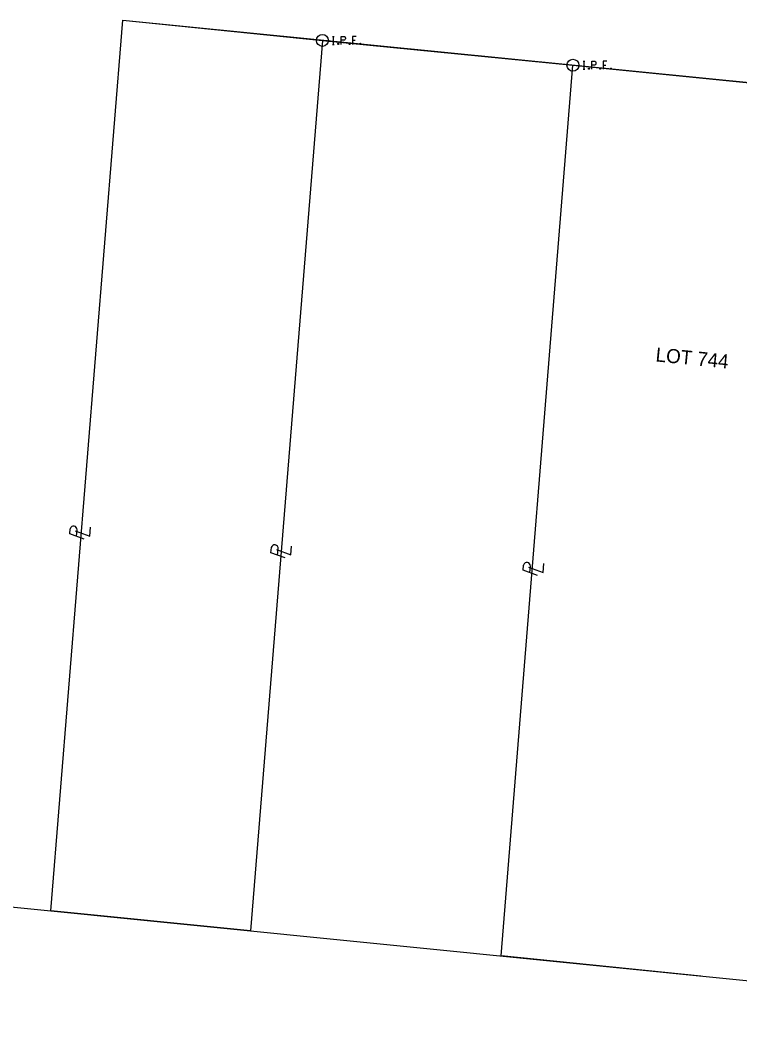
# Model space of a CAD drawing. Extents: x 204354 to 231038, y 361459 to 365260.
# Drawn here: x 220294.5 to 220438, y 363483.6 to 363685.1 of the extents above; entities that cross this region are included whole.
import ezdxf

# ---------------------------------------------------------------- set-up
doc = ezdxf.new("R2010")
doc.units = 0
for name, color, linetype in [('Default', 7, 'Continuous'), ('MD_P_Surface_Finished_Grade', 7, 'Continuous'), ('MD_P_SW_BOT', 7, 'Continuous'), ('PV_P_Walk', 7, 'Continuous')]:
    doc.layers.add(name, color=color, linetype=linetype)

msp = doc.modelspace()

# ---------------------------------------------------------------- linework, layer by layer
at = {"layer": 'MD_P_Surface_Finished_Grade'}
for points in [[(220356.8, 363681.84), (220357.15, 363681.84)], [(220356.98, 363680.24), (220356.98, 363681.84)], [(220358.54, 363680.24), (220358.54, 363681.84), (220359.07, 363681.84), (220359.13, 363681.83), (220359.2, 363681.8), (220359.24, 363681.78), (220359.27, 363681.75), (220359.31, 363681.69), (220359.35, 363681.62), (220359.37, 363681.52), (220359.37, 363681.37), (220359.36, 363681.32), (220359.34, 363681.25), (220359.29, 363681.16), (220359.25, 363681.12), (220359.22, 363681.1), (220359.16, 363681.07), (220359.07, 363681.06), (220358.54, 363681.06)], [(220361.55, 363681.84), (220360.79, 363681.84), (220360.79, 363680.24)], [(220356.8, 363680.24), (220357.15, 363680.24)], [(220357.94, 363680.45), (220357.99, 363680.45), (220358.03, 363680.43), (220358.06, 363680.38), (220358.06, 363680.31), (220358.03, 363680.26), (220357.99, 363680.24), (220357.94, 363680.24), (220357.9, 363680.26), (220357.87, 363680.31), (220357.87, 363680.38), (220357.9, 363680.43), (220357.94, 363680.45)], [(220360.19, 363680.45), (220360.24, 363680.45), (220360.27, 363680.43), (220360.31, 363680.38), (220360.31, 363680.31), (220360.27, 363680.26), (220360.24, 363680.24), (220360.19, 363680.24), (220360.15, 363680.26), (220360.12, 363680.31), (220360.12, 363680.38), (220360.15, 363680.43), (220360.19, 363680.45)], [(220360.79, 363681.06), (220361.33, 363681.06)], [(220362.33, 363680.45), (220362.39, 363680.45), (220362.42, 363680.43), (220362.46, 363680.38), (220362.46, 363680.31), (220362.42, 363680.26), (220362.39, 363680.24), (220362.33, 363680.24), (220362.3, 363680.26), (220362.27, 363680.31), (220362.27, 363680.38), (220362.3, 363680.43), (220362.33, 363680.45)], [(220406.78, 363676.88), (220407.13, 363676.88)], [(220406.96, 363675.28), (220406.96, 363676.88)], [(220407.91, 363675.49), (220407.97, 363675.49), (220408, 363675.47), (220408.04, 363675.41), (220408.04, 363675.35), (220408, 363675.3), (220407.97, 363675.28), (220407.91, 363675.28), (220407.88, 363675.3), (220407.85, 363675.35), (220407.85, 363675.41), (220407.88, 363675.47), (220407.91, 363675.49)], [(220408.52, 363675.28), (220408.52, 363676.88), (220409.05, 363676.88), (220409.11, 363676.86), (220409.18, 363676.84), (220409.22, 363676.81), (220409.25, 363676.79), (220409.29, 363676.72), (220409.33, 363676.66), (220409.35, 363676.56), (220409.35, 363676.41), (220409.34, 363676.36), (220409.31, 363676.28), (220409.27, 363676.2), (220409.23, 363676.16), (220409.19, 363676.13), (220409.14, 363676.11), (220409.05, 363676.09), (220408.52, 363676.09)], [(220410.16, 363675.49), (220410.22, 363675.49), (220410.25, 363675.47), (220410.28, 363675.41), (220410.28, 363675.35), (220410.25, 363675.3), (220410.22, 363675.28), (220410.16, 363675.28), (220410.13, 363675.3), (220410.1, 363675.35), (220410.1, 363675.41), (220410.13, 363675.47), (220410.16, 363675.49)], [(220411.53, 363676.88), (220410.77, 363676.88), (220410.77, 363675.28)], [(220410.77, 363676.09), (220411.31, 363676.09)], [(220412.31, 363675.49), (220412.37, 363675.49), (220412.4, 363675.47), (220412.43, 363675.41), (220412.43, 363675.35), (220412.4, 363675.3), (220412.37, 363675.28), (220412.31, 363675.28), (220412.28, 363675.3), (220412.25, 363675.35), (220412.25, 363675.41), (220412.28, 363675.47), (220412.31, 363675.49)], [(220406.78, 363675.28), (220407.13, 363675.28)]]:
    msp.add_lwpolyline(points, dxfattribs=at)
for centre in [(220354.79, 363681.04), (220404.76, 363676.08)]:
    msp.add_circle(centre, 1.2, dxfattribs=at)
at = {"layer": 'MD_P_SW_BOT'}
for p, q in [((220300.67, 363507.48), (220314.99, 363685.06)), ((220314.99, 363685.06), (220354.79, 363681.04)), ((220354.79, 363681.04), (220340.47, 363503.47)), ((220354.79, 363681.04), (220404.76, 363676.08)), ((220390.45, 363498.5), (220404.76, 363676.08)), ((220404.76, 363676.08), (220494.53, 363667.17)), ((220305.75, 363582.16), (220305.87, 363583.45)), ((220306.45, 363582.91), (220306.45, 363582.91)), ((220345.85, 363578.4), (220345.96, 363579.69)), ((220346.54, 363579.15), (220346.54, 363579.15)), ((220396.16, 363574.92), (220396.27, 363576.21)), ((220396.85, 363575.67), (220396.85, 363575.67)), ((220066.84, 363530.94), (220539.49, 363483.56)), ((220340.47, 363503.47), (220300.67, 363507.48)), ((220430.25, 363494.48), (220390.45, 363498.5))]:
    msp.add_line(p, q, dxfattribs=at)
for points in [[(220307.3, 363581.61), (220304.42, 363582.64), (220304.51, 363583.67)], [(220305.51, 363583.26), (220308.39, 363582.21), (220308.54, 363583.95)], [(220347.4, 363577.84), (220344.51, 363578.88), (220344.61, 363579.91)], [(220345.61, 363579.5), (220348.49, 363578.45), (220348.64, 363580.19)], [(220397.71, 363574.37), (220394.82, 363575.4), (220394.91, 363576.43)], [(220395.92, 363576.02), (220398.79, 363574.97), (220398.95, 363576.71)]]:
    msp.add_lwpolyline(points, dxfattribs=at)
for centre in [(220305.18, 363583.51), (220345.28, 363579.75), (220395.58, 363576.27)]:
    msp.add_arc(centre, 0.69, 355.4688, 166.3259, dxfattribs=at)
at = {"layer": 'PV_P_Walk'}
msp.add_line((220314.99, 363685.06), (220643.05, 363652.36), dxfattribs=at)

# ---------------------------------------------------------------- texts
at = {"layer": 'Default'}
msp.add_text('LOT 744', height=2.8, rotation=354.3411, dxfattribs=at).set_placement((220421.15, 363617.04))

doc.saveas('drawing.dxf')
